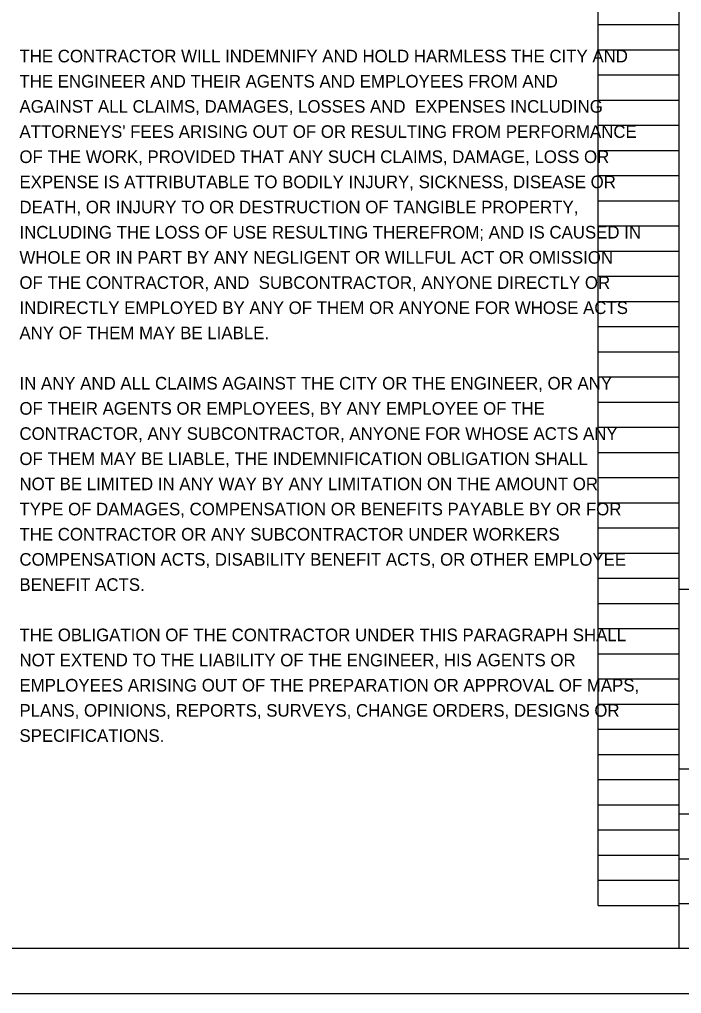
# Model space of a CAD drawing. Extents: x 0 to 37.1, y 0 to 22.
# Drawn here: x 24.66 to 32.03, y 0 to 10.84 of the extents above; entities that cross this region are included whole.
import ezdxf

# ---------------------------------------------------------------- set-up
doc = ezdxf.new("R2010")
doc.units = 0
for name, color, linetype in [('SH_Border', 7, 'Continuous'), ('SH_Cut_Line', 7, 'Continuous'), ('SH_Data', 7, 'Continuous'), ('SH_Text', 7, 'Continuous')]:
    doc.layers.add(name, color=color, linetype=linetype)

msp = doc.modelspace()

# ---------------------------------------------------------------- linework, layer by layer
at = {"layer": 'SH_Border'}
for p, q in [((32, 0.5), (32, 21.5)), ((32, 4.5), (33.5, 4.5)), ((32, 2.5), (33.5, 2.5)), ((32, 2), (33.5, 2)), ((32, 1.5), (33.5, 1.5)), ((32, 1), (33.5, 1))]:
    msp.add_line(p, q, dxfattribs=at)
msp.add_lwpolyline([(1.5, 21.5), (33.5, 21.5), (33.5, 0.5), (1.5, 0.5)], close=True, dxfattribs=at)
at = {"layer": 'SH_Cut_Line'}
msp.add_lwpolyline([(0, 0), (34, 0), (34, 22), (0, 22)], close=True, dxfattribs=at)
at = {"layer": 'SH_Data'}
for p, q in [((31.1, 0.98), (31.1, 21.14)), ((32, 0.98), (32, 21.14)), ((31.1, 10.78), (32, 10.78)), ((31.1, 10.5), (32, 10.5)), ((31.1, 10.22), (32, 10.22)), ((31.1, 9.94), (32, 9.94)), ((31.1, 9.66), (32, 9.66)), ((31.1, 9.38), (32, 9.38)), ((31.1, 9.1), (32, 9.1)), ((31.1, 8.82), (32, 8.82)), ((31.1, 8.54), (32, 8.54)), ((31.1, 8.26), (32, 8.26)), ((31.1, 7.98), (32, 7.98)), ((31.1, 7.7), (32, 7.7)), ((31.1, 7.42), (32, 7.42)), ((31.1, 7.14), (32, 7.14)), ((31.1, 6.86), (32, 6.86)), ((31.1, 6.58), (32, 6.58)), ((31.1, 6.3), (32, 6.3)), ((31.1, 6.02), (32, 6.02)), ((31.1, 5.74), (32, 5.74)), ((31.1, 5.46), (32, 5.46)), ((31.1, 5.18), (32, 5.18)), ((31.1, 4.9), (32, 4.9)), ((31.1, 4.62), (32, 4.62)), ((31.1, 4.34), (32, 4.34)), ((31.1, 4.06), (32, 4.06)), ((31.1, 3.78), (32, 3.78)), ((31.1, 3.5), (32, 3.5)), ((31.1, 3.22), (32, 3.22)), ((31.1, 2.94), (32, 2.94)), ((31.1, 2.66), (32, 2.66)), ((31.1, 2.38), (32, 2.38)), ((31.1, 2.1), (32, 2.1)), ((31.1, 1.82), (32, 1.82)), ((31.1, 1.54), (32, 1.54)), ((31.1, 1.26), (32, 1.26)), ((31.1, 0.98), (32, 0.98))]:
    msp.add_line(p, q, dxfattribs=at)

# ---------------------------------------------------------------- texts
at = {"layer": 'SH_Text'}
for s, p in [('THE CONTRACTOR WILL INDEMNIFY AND HOLD HARMLESS THE CITY AND ', (24.66, 10.36)), ('THE ENGINEER AND THEIR AGENTS AND EMPLOYEES FROM AND ', (24.66, 10.08)), ('AGAINST ALL CLAIMS, DAMAGES, LOSSES AND  EXPENSES INCLUDING ', (24.66, 9.8)), ("ATTORNEYS' FEES ARISING OUT OF OR RESULTING FROM PERFORMANCE ", (24.66, 9.52)), ('OF THE WORK, PROVIDED THAT ANY SUCH CLAIMS, DAMAGE, LOSS OR ', (24.66, 9.24)), ('EXPENSE IS ATTRIBUTABLE TO BODILY INJURY, SICKNESS, DISEASE OR ', (24.66, 8.96)), ('DEATH, OR INJURY TO OR DESTRUCTION OF TANGIBLE PROPERTY, ', (24.66, 8.68)), ('INCLUDING THE LOSS OF USE RESULTING THEREFROM; AND IS CAUSED IN ', (24.66, 8.4)), ('WHOLE OR IN PART BY ANY NEGLIGENT OR WILLFUL ACT OR OMISSION ', (24.66, 8.12)), ('OF THE CONTRACTOR, AND  SUBCONTRACTOR, ANYONE DIRECTLY OR ', (24.66, 7.84)), ('INDIRECTLY EMPLOYED BY ANY OF THEM OR ANYONE FOR WHOSE ACTS ', (24.66, 7.56)), ('ANY OF THEM MAY BE LIABLE.', (24.66, 7.28)), ('IN ANY AND ALL CLAIMS AGAINST THE CITY OR THE ENGINEER, OR ANY ', (24.66, 6.72)), ('OF THEIR AGENTS OR EMPLOYEES, BY ANY EMPLOYEE OF THE ', (24.66, 6.44)), ('CONTRACTOR, ANY SUBCONTRACTOR, ANYONE FOR WHOSE ACTS ANY ', (24.66, 6.16)), ('OF THEM MAY BE LIABLE, THE INDEMNIFICATION OBLIGATION SHALL ', (24.66, 5.88)), ('NOT BE LIMITED IN ANY WAY BY ANY LIMITATION ON THE AMOUNT OR ', (24.66, 5.6)), ('TYPE OF DAMAGES, COMPENSATION OR BENEFITS PAYABLE BY OR FOR ', (24.66, 5.32)), ('THE CONTRACTOR OR ANY SUBCONTRACTOR UNDER WORKERS ', (24.66, 5.04)), ('COMPENSATION ACTS, DISABILITY BENEFIT ACTS, OR OTHER EMPLOYEE ', (24.66, 4.76)), ('BENEFIT ACTS.    ', (24.66, 4.48)), ('THE OBLIGATION OF THE CONTRACTOR UNDER THIS PARAGRAPH SHALL ', (24.66, 3.92)), ('NOT EXTEND TO THE LIABILITY OF THE ENGINEER, HIS AGENTS OR ', (24.66, 3.64)), ('EMPLOYEES ARISING OUT OF THE PREPARATION OR APPROVAL OF MAPS, ', (24.66, 3.36)), ('PLANS, OPINIONS, REPORTS, SURVEYS, CHANGE ORDERS, DESIGNS OR ', (24.66, 3.08)), ('SPECIFICATIONS.', (24.66, 2.8))]:
    msp.add_text(s, height=0.14, dxfattribs=at).set_placement(p)

doc.saveas('drawing.dxf')
